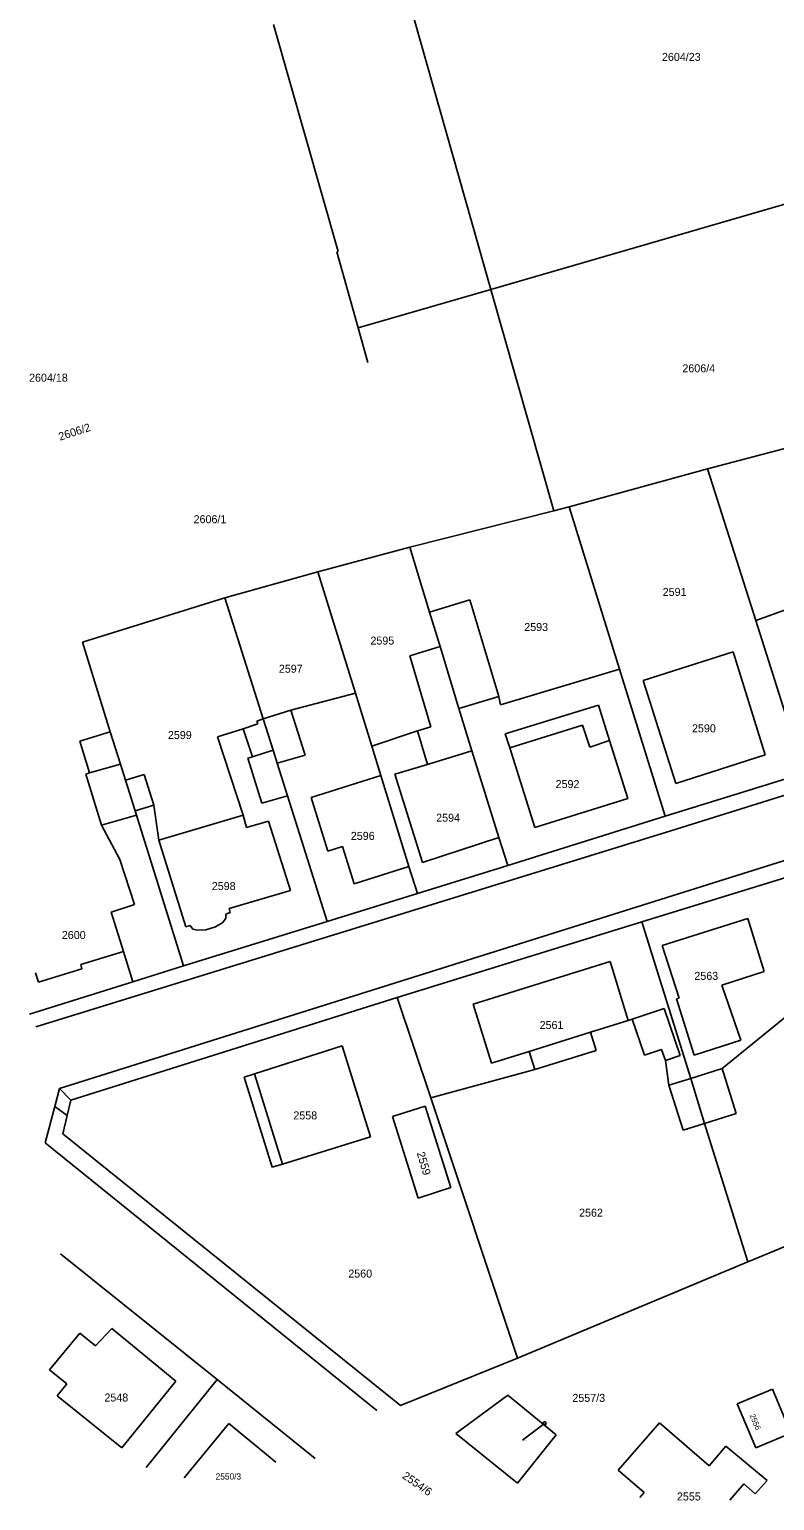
# Model space of a CAD drawing. Extents: x -722132 to -721608, y -1046877 to -1046449.
# Drawn here: x -722131 to -722051.9, y -1046876.8 to -1046720.6 of the extents above; entities that cross this region are included whole.
import ezdxf

# ---------------------------------------------------------------- set-up
doc = ezdxf.new("R2010")
doc.units = 0
for name, color, linetype in [('Vrstva 1', 7, 'Continuous'), ('Vrstva 16', 7, 'Continuous'), ('Vrstva 18', 7, 'Continuous'), ('Vrstva 19', 7, 'Continuous'), ('Vrstva 4', 7, 'Continuous'), ('Vrstva 6', 7, 'Continuous')]:
    doc.layers.add(name, color=color, linetype=linetype)

msp = doc.modelspace()

# ---------------------------------------------------------------- linework, layer by layer
at = {"layer": 'Vrstva 1'}
for p, q in [((-722092.7, -1046710.44), (-722082, -1046748.2)), ((-722049.94, -1046738.91), (-722082, -1046748.2)), ((-722098.37, -1046744.23), (-722098.23, -1046744.19)), ((-722096.1, -1046752.28), (-722098.37, -1046744.23)), ((-722082, -1046748.2), (-722096.1, -1046752.28)), ((-722082, -1046748.2), (-722075.33, -1046771.73)), ((-722095.06, -1046755.97), (-722096.1, -1046752.28)), ((-722090.6, -1046775.6), (-722075.33, -1046771.73)), ((-722075.33, -1046771.73), (-722073.68, -1046771.31)), ((-722080.19, -1046865.65), (-722085.72, -1046869.73)), ((-722075.06, -1046869.86), (-722080.19, -1046865.65)), ((-722085.72, -1046869.73), (-722079.17, -1046875.01)), ((-722079.17, -1046875.01), (-722075.06, -1046869.86))]:
    msp.add_line(p, q, dxfattribs=at)
for points in [[(-722105.07, -1046720.06), (-722098.23, -1046744.19)], [(-722059.02, -1046767.28), (-722039.36, -1046762.1)], [(-722073.68, -1046771.31), (-722059.02, -1046767.28)], [(-722059.02, -1046767.28), (-722053.89, -1046783.38)], [(-722073.68, -1046771.31), (-722068.33, -1046788.55)], [(-722100.36, -1046778.22), (-722090.6, -1046775.6)], [(-722090.6, -1046775.6), (-722088.51, -1046782.48)], [(-722110.26, -1046780.96), (-722100.36, -1046778.22)], [(-722100.36, -1046778.22), (-722096.37, -1046791.08)], [(-722053.89, -1046783.38), (-722038.33, -1046777.78)], [(-722125.36, -1046785.69), (-722110.26, -1046780.96)], [(-722110.26, -1046780.96), (-722106.18, -1046793.83)], [(-722088.51, -1046782.48), (-722084.25, -1046781.16)], [(-722084.25, -1046781.16), (-722081.16, -1046791.45)], [(-722088.51, -1046782.48), (-722087.4, -1046786.13)], [(-722053.89, -1046783.38), (-722048.73, -1046799.58)], [(-722125.36, -1046785.69), (-722122.42, -1046795.18)], [(-722090.62, -1046787.13), (-722087.4, -1046786.13)], [(-722087.4, -1046786.13), (-722085.4, -1046792.71)], [(-722090.62, -1046787.13), (-722088.36, -1046794.67)], [(-722065.85, -1046789.75), (-722056.27, -1046786.71)], [(-722056.27, -1046786.71), (-722052.89, -1046797.65)], [(-722080.97, -1046792.33), (-722068.33, -1046788.55)], [(-722068.33, -1046788.55), (-722063.49, -1046804.15)], [(-722103.25, -1046792.9), (-722096.37, -1046791.08)], [(-722096.37, -1046791.08), (-722094.63, -1046796.71)], [(-722065.85, -1046789.75), (-722062.36, -1046800.69)], [(-722085.4, -1046792.71), (-722084.04, -1046797.2)], [(-722081.16, -1046791.45), (-722080.97, -1046792.33)], [(-722108.29, -1046794.89), (-722106.76, -1046794.36)], [(-722106.86, -1046794.05), (-722106.18, -1046793.83)], [(-722106.86, -1046794.05), (-722106.76, -1046794.36)], [(-722106.18, -1046793.83), (-722103.25, -1046792.9)], [(-722106.18, -1046793.83), (-722105.12, -1046797.16)], [(-722125.65, -1046796.2), (-722122.42, -1046795.18)], [(-722122.42, -1046795.18), (-722121.32, -1046798.63)], [(-722111.02, -1046795.74), (-722108.29, -1046794.89)], [(-722111.02, -1046795.74), (-722108.3, -1046804.03)], [(-722094.63, -1046796.71), (-722089.78, -1046795.09)], [(-722089.78, -1046795.09), (-722088.36, -1046794.67)], [(-722125.65, -1046796.2), (-722124.62, -1046799.56)], [(-722105.12, -1046797.16), (-722104.68, -1046798.53)], [(-722094.63, -1046796.71), (-722093.69, -1046799.84)], [(-722084.04, -1046797.2), (-722081.15, -1046806.43)], [(-722121.32, -1046798.63), (-722120.78, -1046800.34)], [(-722104.68, -1046798.53), (-722103.58, -1046802)], [(-722062.36, -1046800.69), (-722052.89, -1046797.65)], [(-722125.01, -1046799.68), (-722124.62, -1046799.56)], [(-722125.01, -1046799.68), (-722123.35, -1046805.11)], [(-722120.78, -1046800.34), (-722118.82, -1046799.73)], [(-722120.78, -1046800.34), (-722119.76, -1046803.6)], [(-722118.82, -1046799.73), (-722117.77, -1046802.98)], [(-722093.69, -1046799.84), (-722090.7, -1046809.49)], [(-722063.49, -1046804.15), (-722048.73, -1046799.58)], [(-722103.58, -1046802), (-722099.37, -1046815.33)], [(-722119.76, -1046803.6), (-722119.63, -1046804.04)], [(-722117.77, -1046802.98), (-722117.26, -1046806.69)], [(-722123.35, -1046805.11), (-722121.38, -1046808.75)], [(-722119.63, -1046804.04), (-722114.62, -1046820.06)], [(-722117.26, -1046806.69), (-722108.3, -1046804.03)], [(-722080.21, -1046809.39), (-722063.49, -1046804.15)], [(-722081.15, -1046806.43), (-722080.21, -1046809.39)], [(-722090.7, -1046809.49), (-722089.79, -1046812.35)], [(-722089.79, -1046812.35), (-722080.21, -1046809.39)], [(-722065.97, -1046815.38), (-722049.78, -1046810.38)], [(-722099.37, -1046815.33), (-722089.79, -1046812.35)], [(-722114.62, -1046820.06), (-722099.37, -1046815.33)], [(-722091.94, -1046823.42), (-722065.97, -1046815.38)], [(-722065.97, -1046815.38), (-722060.79, -1046832.01)], [(-722125.55, -1046819.92), (-722121.02, -1046818.51)], [(-722121.02, -1046818.51), (-722120.01, -1046821.74)], [(-722130.35, -1046820.79), (-722130.04, -1046821.78)], [(-722130.04, -1046821.78), (-722125.42, -1046820.35)], [(-722125.55, -1046819.92), (-722125.42, -1046820.35)], [(-722120.01, -1046821.74), (-722114.62, -1046820.06)], [(-722130.99, -1046825.17), (-722120.01, -1046821.74)], [(-722057.45, -1046830.97), (-722046.09, -1046821.73)], [(-722126.6, -1046834.33), (-722091.94, -1046823.42)], [(-722091.94, -1046823.42), (-722088.39, -1046834.06)], [(-722071.42, -1046827.11), (-722067.41, -1046825.87)], [(-722071.42, -1046827.11), (-722070.82, -1046829.03)], [(-722067.41, -1046825.87), (-722067.01, -1046825.73)], [(-722067.01, -1046825.73), (-722065.68, -1046829.54)], [(-722107.11, -1046831.53), (-722097.79, -1046828.56)], [(-722097.79, -1046828.56), (-722094.79, -1046838.2)], [(-722077.33, -1046831.06), (-722070.82, -1046829.03)], [(-722065.68, -1046829.54), (-722063.9, -1046828.92)], [(-722063.9, -1046828.92), (-722063.48, -1046830.12)], [(-722063.48, -1046830.12), (-722063.1, -1046832.73)], [(-722108.21, -1046831.87), (-722107.11, -1046831.53)], [(-722108.21, -1046831.87), (-722105.22, -1046841.44)], [(-722088.39, -1046834.06), (-722077.33, -1046831.06)], [(-722057.45, -1046830.97), (-722055.96, -1046835.74)], [(-722127.8, -1046833.06), (-722126.6, -1046834.33)], [(-722063.1, -1046832.73), (-722061.6, -1046837.5)], [(-722060.79, -1046832.01), (-722059.31, -1046836.78)], [(-722126.99, -1046835.94), (-722126.6, -1046834.33)], [(-722092.44, -1046836.06), (-722088.98, -1046834.97)], [(-722088.98, -1046834.97), (-722086.24, -1046843.6)], [(-722088.39, -1046834.06), (-722079.17, -1046861.71)], [(-722127.46, -1046837.88), (-722126.99, -1046835.94)], [(-722092.44, -1046836.06), (-722089.73, -1046844.71)], [(-722059.31, -1046836.78), (-722055.96, -1046835.74)], [(-722127.46, -1046837.88), (-722091.59, -1046866.76)], [(-722061.6, -1046837.5), (-722059.31, -1046836.78)], [(-722059.31, -1046836.78), (-722054.73, -1046851.47)], [(-722104.12, -1046841.1), (-722094.79, -1046838.2)], [(-722105.22, -1046841.44), (-722104.12, -1046841.1)], [(-722089.73, -1046844.71), (-722086.24, -1046843.6)], [(-722054.73, -1046851.47), (-722038.94, -1046844.98)], [(-722111.07, -1046863.99), (-722127.7, -1046850.62)], [(-722079.17, -1046861.71), (-722054.73, -1046851.47)], [(-722128.86, -1046862.97), (-722125.63, -1046859.07)], [(-722125.63, -1046859.07), (-722123.97, -1046860.41)], [(-722123.97, -1046860.41), (-722122.24, -1046858.58)], [(-722122.24, -1046858.58), (-722115.44, -1046864.15)], [(-722128.86, -1046862.97), (-722127.01, -1046864.45)], [(-722091.59, -1046866.76), (-722079.17, -1046861.71)], [(-722128.03, -1046865.71), (-722127.01, -1046864.45)], [(-722121.18, -1046871.25), (-722115.44, -1046864.15)], [(-722111.07, -1046863.99), (-722118.61, -1046873.33)], [(-722100.64, -1046872.37), (-722111.07, -1046863.99)], [(-722128.03, -1046865.71), (-722121.18, -1046871.25)], [(-722055.87, -1046866.57), (-722052.12, -1046865.02)], [(-722052.12, -1046865.02), (-722050.17, -1046869.67)], [(-722055.87, -1046866.57), (-722053.89, -1046871.23)], [(-722114.58, -1046874.42), (-722109.81, -1046868.65)], [(-722109.81, -1046868.65), (-722104.84, -1046872.75)], [(-722068.48, -1046873.62), (-722064.1, -1046868.58)], [(-722064.1, -1046868.58), (-722058.82, -1046873.16)], [(-722053.89, -1046871.23), (-722050.17, -1046869.67)], [(-722058.82, -1046873.16), (-722057.07, -1046871.08)], [(-722057.07, -1046871.08), (-722052.68, -1046874.7)], [(-722068.48, -1046873.62), (-722065.72, -1046875.97)], [(-722053.93, -1046876.11), (-722052.68, -1046874.7)], [(-722066.19, -1046876.52), (-722065.72, -1046875.97)]]:
    msp.add_lwpolyline(points, dxfattribs=at)
at = {"layer": 'Vrstva 16'}
msp.add_lwpolyline([(-722078.64, -1046870.43), (-722076.32, -1046868.65)], dxfattribs=at)
msp.add_circle((-722076.32, -1046868.65), 0.175, dxfattribs=at)
at = {"layer": 'Vrstva 4'}
for points in [[(-722062.88, -1046805.71), (-721970.1, -1046776.68)], [(-722060.86, -1046812.01), (-721966.51, -1046782.33)], [(-722085.4, -1046792.71), (-722081.16, -1046791.45)], [(-722080.49, -1046795.4), (-722070.58, -1046792.37)], [(-722070.58, -1046792.37), (-722069.4, -1046796.13)], [(-722103.25, -1046792.9), (-722101.73, -1046797.68)], [(-722108.29, -1046794.89), (-722107.32, -1046797.84)], [(-722089.78, -1046795.09), (-722088.72, -1046798.65)], [(-722080.49, -1046795.4), (-722079.99, -1046796.89)], [(-722079.99, -1046796.89), (-722072.26, -1046794.5)], [(-722072.26, -1046794.5), (-722071.51, -1046796.82)], [(-722107.32, -1046797.84), (-722105.12, -1046797.16)], [(-722088.72, -1046798.65), (-722084.04, -1046797.2)], [(-722079.99, -1046796.89), (-722077.35, -1046805.36)], [(-722071.51, -1046796.82), (-722069.4, -1046796.13)], [(-722069.4, -1046796.13), (-722067.48, -1046802.28)], [(-722124.62, -1046799.56), (-722121.32, -1046798.63)], [(-722107.8, -1046798), (-722107.32, -1046797.84)], [(-722107.8, -1046798), (-722106.32, -1046802.78)], [(-722104.68, -1046798.53), (-722101.73, -1046797.68)], [(-722092.19, -1046799.69), (-722088.72, -1046798.65)], [(-722101.08, -1046802.17), (-722093.69, -1046799.84)], [(-722092.19, -1046799.69), (-722089.27, -1046809.06)], [(-722106.32, -1046802.78), (-722103.58, -1046802)], [(-722101.08, -1046802.17), (-722099.32, -1046807.86)], [(-722119.76, -1046803.6), (-722117.77, -1046802.98)], [(-722077.35, -1046805.36), (-722067.48, -1046802.28)], [(-722123.35, -1046805.11), (-722119.63, -1046804.04)], [(-722108.3, -1046804.03), (-722107.94, -1046805.35)], [(-722107.94, -1046805.35), (-722105.6, -1046804.7)], [(-722105.6, -1046804.7), (-722103.29, -1046812.03)], [(-722130.3, -1046826.54), (-722062.88, -1046805.71)], [(-722117.26, -1046806.69), (-722114.39, -1046815.9)], [(-722089.27, -1046809.06), (-722081.15, -1046806.43)], [(-722099.32, -1046807.86), (-722097.76, -1046807.38)], [(-722097.76, -1046807.38), (-722096.53, -1046811.34)], [(-722121.38, -1046808.75), (-722119.82, -1046813.53)], [(-722096.53, -1046811.34), (-722090.7, -1046809.49)], [(-722127.8, -1046833.06), (-722060.86, -1046812.01)], [(-722109.8, -1046813.97), (-722103.29, -1046812.03)], [(-722122.33, -1046814.35), (-722119.82, -1046813.53)], [(-722122.33, -1046814.35), (-722121.02, -1046818.51)], [(-722110.15, -1046814.55), (-722109.67, -1046814.4)], [(-722110.15, -1046814.55), (-722110.14, -1046815)], [(-722109.8, -1046813.97), (-722109.67, -1046814.4)], [(-722114.39, -1046815.9), (-722113.93, -1046815.75)], [(-722113.93, -1046815.75), (-722113.63, -1046816.16)], [(-722113.63, -1046816.16), (-722113.16, -1046816.27)], [(-722113.16, -1046816.27), (-722112.26, -1046816.23)], [(-722112.26, -1046816.23), (-722111.24, -1046815.91)], [(-722111.24, -1046815.91), (-722110.47, -1046815.43)], [(-722110.47, -1046815.43), (-722110.14, -1046815)], [(-722063.81, -1046817.88), (-722054.73, -1046815.01)], [(-722054.73, -1046815.01), (-722052.98, -1046820.65)], [(-722063.81, -1046817.88), (-722062.02, -1046823.47)], [(-722083.87, -1046824.12), (-722069.35, -1046819.58)], [(-722069.35, -1046819.58), (-722067.41, -1046825.87)], [(-722057.47, -1046822.11), (-722052.98, -1046820.65)], [(-722057.47, -1046822.11), (-722055.46, -1046827.94)], [(-722062.31, -1046823.56), (-722062.02, -1046823.47)], [(-722062.31, -1046823.56), (-722060.41, -1046829.52)], [(-722083.87, -1046824.12), (-722081.92, -1046830.37)], [(-722067.01, -1046825.73), (-722063.59, -1046824.59)], [(-722063.59, -1046824.59), (-722061.92, -1046829.58)], [(-722077.93, -1046829.13), (-722071.42, -1046827.11)], [(-722060.41, -1046829.52), (-722055.46, -1046827.94)], [(-722081.92, -1046830.37), (-722077.93, -1046829.13)], [(-722077.93, -1046829.13), (-722077.33, -1046831.06)], [(-722063.48, -1046830.12), (-722061.92, -1046829.58)], [(-722107.11, -1046831.53), (-722104.12, -1046841.1)], [(-722060.79, -1046832.01), (-722057.45, -1046830.97)], [(-722128.31, -1046835), (-722127.8, -1046833.06)], [(-722063.1, -1046832.73), (-722060.79, -1046832.01)], [(-722129.33, -1046838.83), (-722128.31, -1046835)], [(-722129.33, -1046838.83), (-722094.11, -1046867.29)], [(-722056.65, -1046876.79), (-722055.16, -1046875.07)], [(-722055.16, -1046875.07), (-722053.93, -1046876.11)]]:
    msp.add_lwpolyline(points, dxfattribs=at)
at = {"layer": 'Vrstva 6'}
msp.add_lwpolyline([(-722128.31, -1046835), (-722126.99, -1046835.94)], dxfattribs=at)

# ---------------------------------------------------------------- texts
at = {"layer": 'Vrstva 16'}
msp.add_text('2557/3', height=0.85, dxfattribs=at).set_placement((-722073.35, -1046866.36))
at = {"layer": 'Vrstva 18'}
for s, p in [('2604/23', (-722063.84, -1046723.94)), ('2606/4', (-722061.67, -1046757.01)), ('2606/1', (-722113.56, -1046773.04)), ('2591', (-722063.76, -1046780.76)), ('2593', (-722078.46, -1046784.49)), ('2595', (-722094.79, -1046785.93)), ('2597', (-722104.51, -1046788.92)), ('2599', (-722116.29, -1046795.96)), ('2562', (-722072.64, -1046846.69)), ('2560', (-722097.14, -1046853.16))]:
    msp.add_text(s, height=0.85, dxfattribs=at).set_placement(p)
msp.add_text('2554/6', height=0.85, rotation=325.1174, dxfattribs=at).set_placement((-722091.48, -1046874.4))
at = {"layer": 'Vrstva 19'}
for s, height, p in [('2604/18', 0.85, (-722131.03, -1046758.01)), ('2590', 0.85, (-722060.65, -1046795.25)), ('2592', 0.85, (-722075.13, -1046801.17)), ('2594', 0.85, (-722087.81, -1046804.74)), ('2596', 0.85, (-722096.87, -1046806.67)), ('2598', 0.85, (-722111.63, -1046812)), ('2600', 0.85, (-722127.55, -1046817.2)), ('2563', 0.85, (-722060.4, -1046821.54)), ('2561', 0.85, (-722076.83, -1046826.76)), ('2558', 0.85, (-722102.97, -1046836.36)), ('2548', 0.85, (-722123.03, -1046866.32)), ('2557/3', 0.1, (-722078.64, -1046870.43)), ('2550/3', 0.66, (-722111.22, -1046874.61)), ('2555', 0.85, (-722062.25, -1046876.83))]:
    msp.add_text(s, height=height, dxfattribs=at).set_placement(p)
for s, height, rotation, p in [('2606/2', 0.85, 18, (-722127.73, -1046764.28)), ('2559', 0.85, 286.3377, (-722089.88, -1046839.94)), ('2556', 0.595, 292.9949, (-722054.55, -1046867.79))]:
    msp.add_text(s, height=height, rotation=rotation, dxfattribs=at).set_placement(p)

doc.saveas('drawing.dxf')
